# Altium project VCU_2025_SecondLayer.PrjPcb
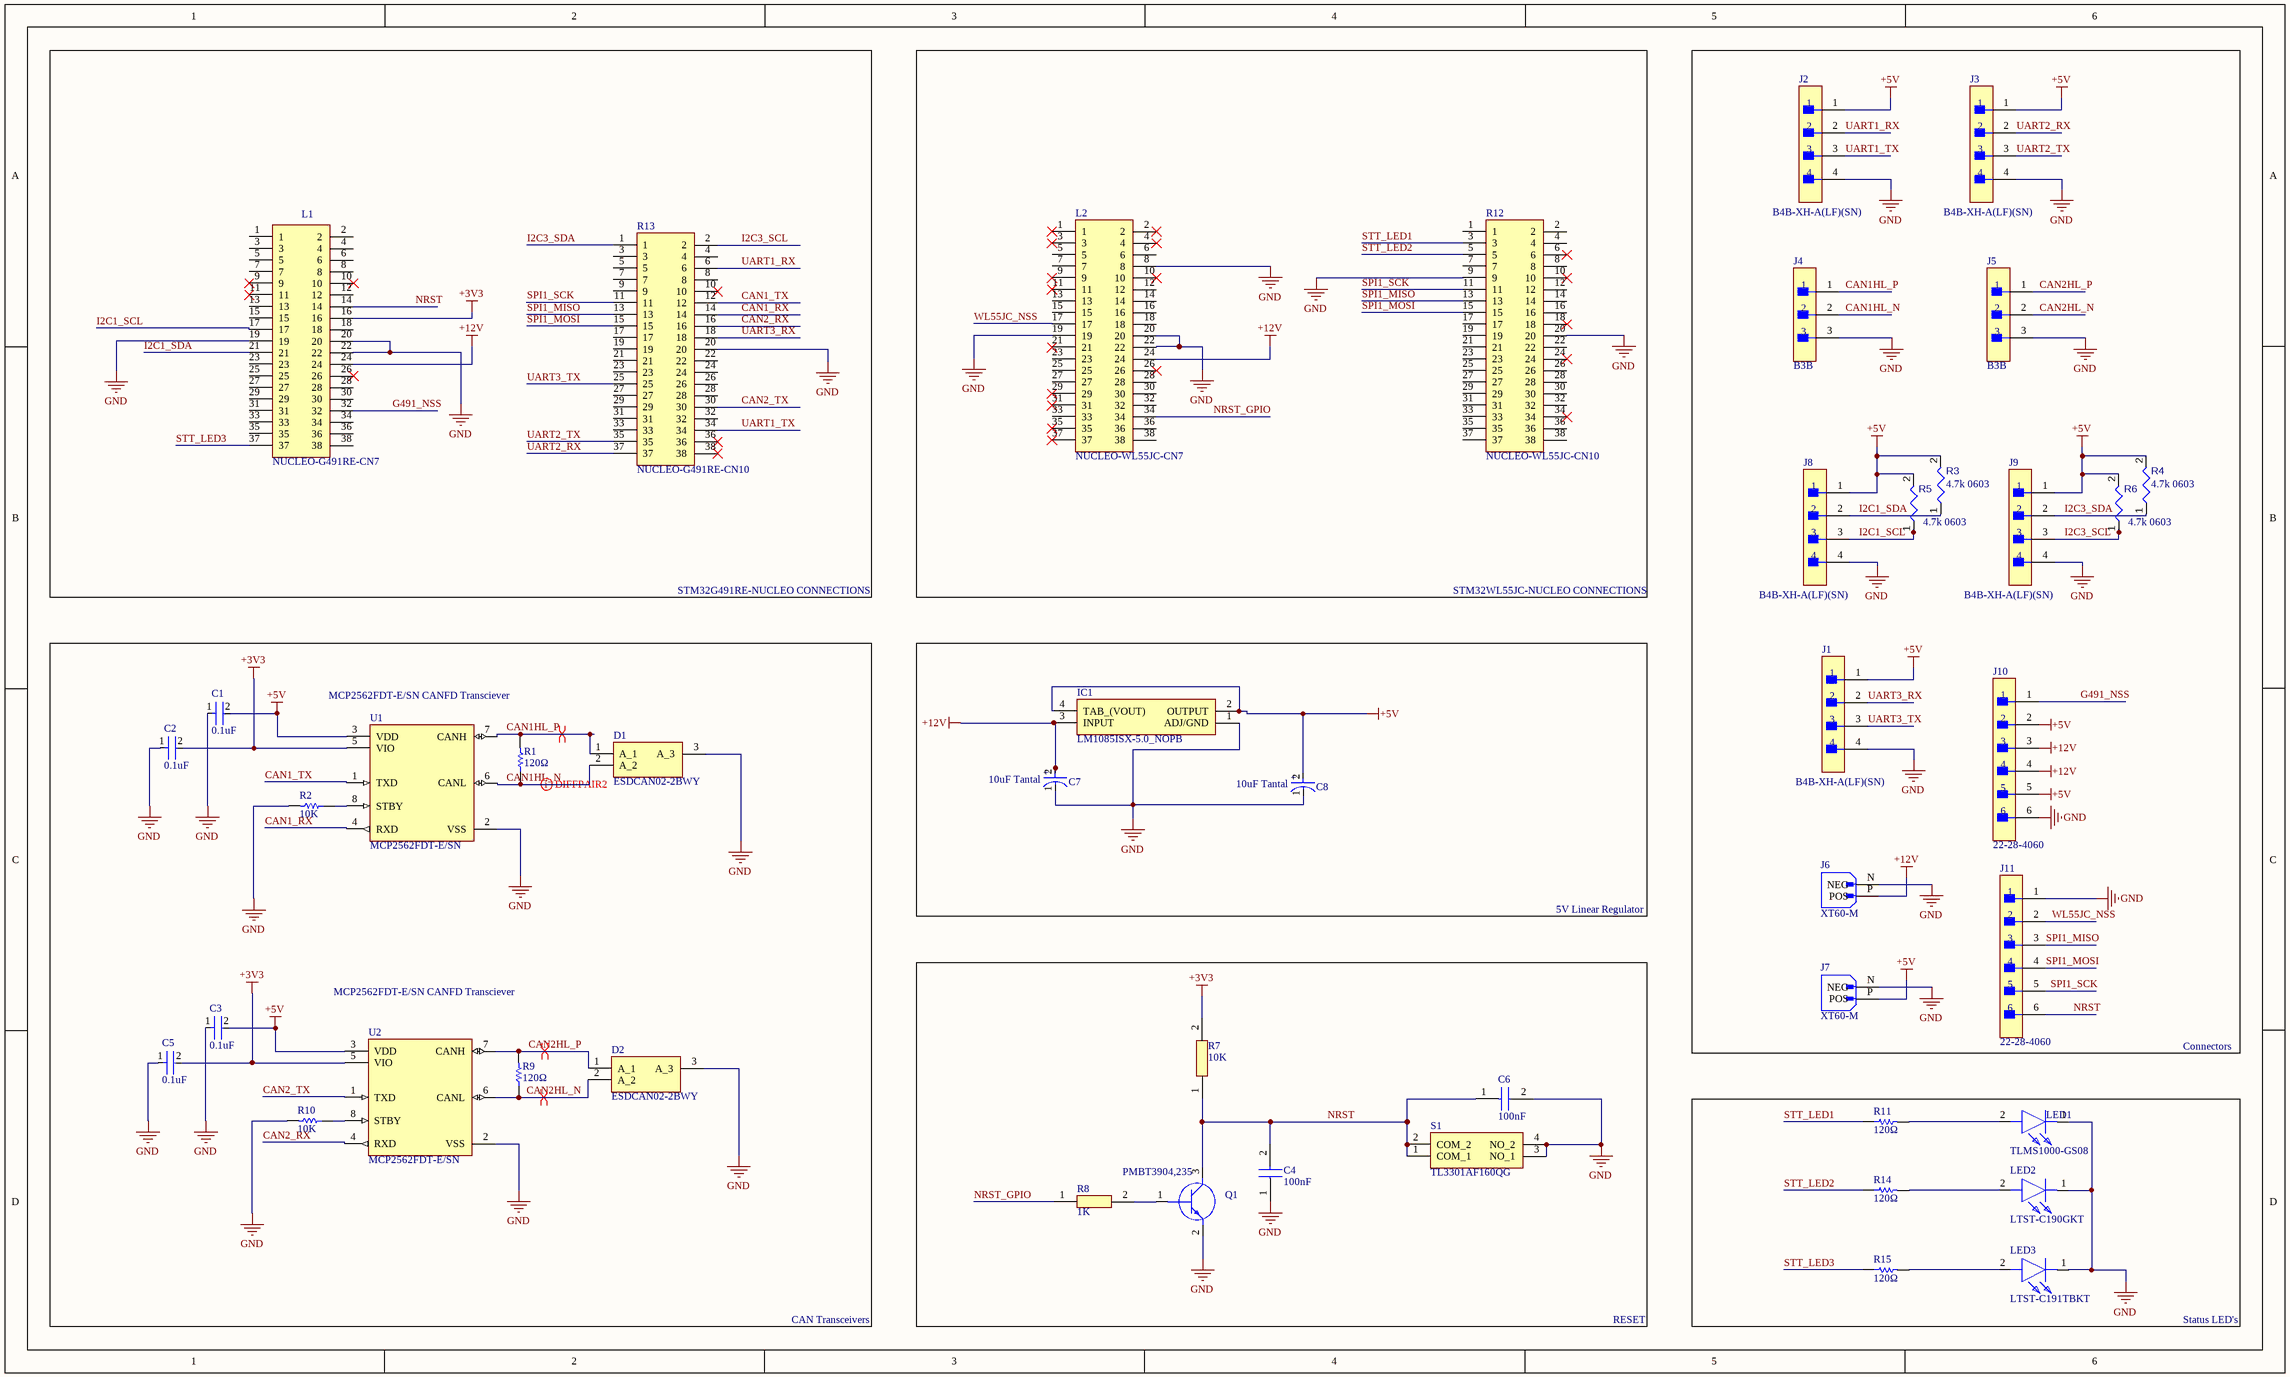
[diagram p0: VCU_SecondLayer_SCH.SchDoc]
1 sheet, 46 parts. Net scope: global (net labels, ports and power ports of the same name join across sheets).
Board file: VCU_SecondLayer_PCB.PcbDoc

## Sheet VCU_SecondLayer_SCH.SchDoc
size 500 x 299 mm; SheetNumber: 1; SheetTotal: 1

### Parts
C1  0.1uF  [FP-C0603C-CF-MFG]
C2  0.1uF  [FP-C0603C-CF-MFG]
C3  0.1uF  [FP-C0603C-CF-MFG]
C4  100nF  [CAPC1608X97N]
C5  0.1uF  [FP-C0603C-CF-MFG]
C6  100nF  [CAPC1608X97N]
C7  10uF Tantal  [FP-T491D-MFG]
C8  10uF Tantal  [FP-T491D-MFG]
D1  ESDCAN02-2BWY  [SOT65P210X110-3N]
D2  ESDCAN02-2BWY  [SOT65P210X110-3N]
IC1  LM1085ISX-5.0_NOPB  [KTT0003B]
J1  B4B-XH-A(LF)(SN)  [FP-B4B-XH-A_LF_SN-MFG]
J2  B4B-XH-A(LF)(SN)  [FP-B4B-XH-A_LF_SN-MFG]
J3  B4B-XH-A(LF)(SN)  [FP-B4B-XH-A_LF_SN-MFG]
J4  B3B  [FP-B3B-ZR_LF_SN-MFG]
J5  B3B  [FP-B3B-ZR_LF_SN-MFG]
J6  XT60-M  [XT60-M-Footprint-1]
J7  XT60-M  [XT60-M-Footprint-1]
J8  B4B-XH-A(LF)(SN)  [FP-B4B-XH-A_LF_SN-MFG]
J9  B4B-XH-A(LF)(SN)  [FP-B4B-XH-A_LF_SN-MFG]
J10  22-28-4060  [FP-22-28-4060-MFG]
J11  22-28-4060  [FP-22-28-4060-MFG]
L1  NUCLEO-G491RE-CN7  [CES-119-XX-X-D]
L2  NUCLEO-WL55JC-CN7  [CES-119-XX-X-D]
LED1  TLMS1000-GS08  [LEDC1608X65N]
LED2  LTST-C190GKT  [LEDC1608X90N]
LED3  LTST-C191TBKT  [LEDC1608X65N]
Q1  PMBT3904,235  [SOT95P230X110-3N]
R1  120Ω  [RESC1609X55X30ML15T15]
R2  10K  [RESC1609X55X30ML15T15]
R3  value 4.7k 0603  [RESC1608X55X25ML10T15]  (hidden comment: Resistor 10k +/-1% 0603 100 mW)
R4  value 4.7k 0603  [RESC1608X55X25ML10T15]  (hidden comment: Resistor 10k +/-1% 0603 100 mW)
R5  value 4.7k 0603  [RESC1608X55X25ML10T15]  (hidden comment: Resistor 10k +/-1% 0603 100 mW)
R6  value 4.7k 0603  [RESC1608X55X25ML10T15]  (hidden comment: Resistor 10k +/-1% 0603 100 mW)
R7  10K  [RESC1608X55N]
R8  1K  [RESC1608X55N]
R9  120Ω  [RESC1609X55X30ML15T15]
R10  10K  [RESC1609X55X30ML15T15]
R11  120Ω  [RESC1609X55X30ML15T15]
R12  NUCLEO-WL55JC-CN10  [CES-119-XX-X-D]
R13  NUCLEO-G491RE-CN10  [CES-119-XX-X-D]
R14  120Ω  [RESC1609X55X30ML15T15]
R15  120Ω  [RESC1609X55X30ML15T15]
S1  TL3301AF160QG  [TL3301AF160QG]
U1  MCP2562FDT-E/SN  [FP-C04-057-SN-MFG]
U2  MCP2562FDT-E/SN  [FP-C04-057-SN-MFG]

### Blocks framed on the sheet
STM32G491RE-NUCLEO CONNECTIONS: L1 R13
STM32WL55JC-NUCLEO CONNECTIONS: L2 R12
Connectors: J1-J11 R3-R6
5V Linear Regulator: C7 C8 IC1
RESET: C4 C6 Q1 R7 R8 S1
Status LED's: LED1-LED3 R11 R14 R15

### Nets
+3V3: C2.2 C5.2 L1.16 R7.2 U1.5(VIO) U2.5(VIO)
+5V: C1.2 C3.2 C8.2(A) IC1.2(OUTPUT) IC1.4(TAB_(VOUT)) J1.1 J2.1 J3.1 J7.P(POS) J8.1 J9.1 J10.2 J10.5 R3.2 R4.2 R5.2 R6.2 U1.3(VDD) U2.3(VDD)
+12V: C7.2(A) IC1.3(INPUT) J6.P(POS) J10.3 J10.4 L1.24 L2.24
GND: C1.1 C2.1 C3.1 C4.1 C5.1 C6.2 C7.1(C) C8.1(C) D1.3(A_3) D2.3(A_3) IC1.1(ADJ/GND) J1.4 J2.4 J3.4 J4.3 J5.3 J6.N(NEG) J7.N(NEG) J8.4 J9.4 J10.6 J11.1 L1.19 L1.20 L1.22 L2.8 L2.19 L2.20 L2.22 LED1.1(K) LED2.1(K) LED3.1(K) Q1.2(E) R2.2 R10.2 R12.9 R12.20 R13.20 S1.3(NO_1) S1.4(NO_2) U1.2(VSS) U2.2(VSS)
CAN1_RX: R13.14 U1.4(RXD)
CAN1_TX: R13.12 U1.1(TXD)
CAN1HL_N: D1.2(A_2) J4.2 R1.1 U1.6(CANL)
CAN1HL_P: D1.1(A_1) J4.1 R1.2 U1.7(CANH)
CAN2_RX: R13.16 U2.4(RXD)
CAN2_TX: R13.30 U2.1(TXD)
CAN2HL_N: D2.2(A_2) J5.2 R9.1 U2.6(CANL)
CAN2HL_P: D2.1(A_1) J5.1 R9.2 U2.7(CANH)
G491_NSS: J10.1 L1.32
I2C1_SCL: J8.3 L1.17 R5.1
I2C1_SDA: J8.2 L1.21 R3.1
I2C3_SCL: J9.3 R6.1 R13.2
I2C3_SDA: J9.2 R4.1 R13.1
NRST: C4.2 C6.1 J11.6 L1.14 Q1.3(C) R7.1 S1.1(COM_1) S1.2(COM_2)
NRST_GPIO: L2.34 R8.1
SPI1_MISO: J11.3 R12.13 R13.13
SPI1_MOSI: J11.4 R12.15 R13.15
SPI1_SCK: J11.5 R12.11 R13.11
STT_LED1: R11.1 R12.3
STT_LED2: R12.5 R14.1
STT_LED3: L1.37 R15.1
UART1_RX: J2.2 R13.6
UART1_TX: J2.3 R13.34
UART2_RX: J3.2 R13.37
UART2_TX: J3.3 R13.35
UART3_RX: J1.2 R13.18
UART3_TX: J1.3 R13.25
WL55JC_NSS: J11.2 L2.17
NetLED1_2: LED1.2(A) R11.2
NetLED2_2: LED2.2(A) R14.2
NetLED3_2: LED3.2(A) R15.2
NetQ1_1: Q1.1(B) R8.2
NetR2_1: R2.1 U1.8(STBY)
NetR10_1: R10.1 U2.8(STBY)

Not connected (* = marked no-connect by the designer): L1 1 2 3 4 5 6 7 8 9* 10* 11* 12 13 15 18 23 25 26* 27 28 29 30 31 33 34 35 36 38; L2 1* 2* 3* 4* 5 6 7 9* 10* 11* 12 13 14 15 16 18 21* 23 25 26* 27 28 29* 30 31* 32 33 35* 36 37* 38; R12 1 2 4 6* 7 8 10* 12 14 16 17 18* 19 21 22 23 24* 25 26 27 28 29 30 31 32 33 34* 35 36 37 38; R13 3 4 5 7 8 9 10* 17 19 21 22 23 24 26 27 28 29 31 32 33 36* 38*

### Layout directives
differential pair: CAN1HL_N, CAN1HL_P, CAN2HL_N, CAN2HL_P

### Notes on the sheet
- MCP2562FDT-E/SN CANFD Transciever
- CAN Transceivers

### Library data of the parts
C1-C3 C5 = CMP-2006-03068-2: CAP CER 0.1UF 50V 20% X7R 0603; Manufacturer Part Number: C0603C104M5RACTU; Manufacturer: KEMET; Material: Ceramic; Tolerance: 0.2; Value: 0.10 μF; Temperature Coefficient: 30ppm/°C; Automotive Grade: Grade 1
C4 C6 = VJ0603Y104JXJAC: Manufacturer_Name: Vishay
C7 C8 = CMP-001-00086-1: Cap Tant Solid 10uF 25V D CASE 10% (7.3 X 4.3 X 2.8mm) Inward L SMD 7343-31 1 Ohm 125C T/R / T491D106K025AT
D1 D2 = ESDCAN02-2BWY: TVS Diode (Bi-directional); Manufacturer_Name: STMicroelectronics
IC1 = LM1085ISX-5.0_NOPB: Integrated Circuit; Manufacturer_Name: Texas Instruments; Manufacturer_Part_Number: LM1085ISX-5.0/NOPB
J1-J3 J8 J9 = CMP-002-00072-1: Header for PCB; pitch 2.50mm; 4-contacts; THT male; top entry; 250V/3A
J4 J5 = CMP-002-00073-3: CONN HEADER ZH TOP 3POS
J6 J7 = CMP-002-00074-2: XT60 Male Connector
J10 J11 = CMP-04776-000763-1: CONN HEADER VERT 6POS 2.54MM; Voltage Rating: 250V; Current Rating: 4A; Number of Contacts: 6; Max Voltage Rating (DC): 250.25kV; Gender: Male; Contact Resistance: 20mR; Connector Type: Male Pin
L1 L2 R12 R13 = CES-119-02-T-D: Connector; Manufacturer_Name: SAMTEC
LED1 = TLMS1000-GS08: LED; Manufacturer_Name: Vishay
LED2 = LTST-C190GKT: LED; Manufacturer_Name: Lite-On
LED3 = LTST-C191TBKT: LED; Manufacturer_Name: Lite-On
Q1 = PMBT3904,235: Transistor BJT NPN; Manufacturer_Name: Nexperia
R1 R9 R11 R14 R15 = CMP-2000-00213-2: Chip Resistor, 120 Ohm, +/- 1%, 0.1 W, -55 to 155 degC, 0603 (1608 Metric), RoHS, Tape and Reel; Manufacturer: Panasonic; Power Rating: 100mW; Voltage Rating (DC): 75V; Resistance: 120Ohm; Temperature Coefficient: 100ppm/degreesC
R2 R10 = CMP-2000-00213-2: RC0603FR0710KL 0603 10K Resistor; Manufacturer: Panasonic; Tolerance: 1%; Power Rating: 100mW; Voltage Rating (DC): 75V; Resistance: 120Ohm; Temperature Coefficient: 100ppm/degreesC
R3-R6 = CMP-009-00017-5: Chip Resistor, 10 KOhm, +/- 1%, 01 W, -55 to 155 degC, 0603 (1608 Metric) / RC0603FR-0710KL; Voltage Rating: 50V; Power: 100mW
R7 = RC0603FR0710KL: Manufacturer_Name: KEMET
R8 = RC0603FR-071KL: Manufacturer_Name: YAGEO
S1 = TL3301AF160QG: Switch; Manufacturer_Name: E-Switch
U1 U2 = CMP-06279-000005-1: IC TRANSCEIVER 1/1 8SOIC; Operating Supply Current: 70mA; Data Rate: 8Mbps; Number of Transceivers: 1; Receiver Hysteresis: 200mV; Max Supply Voltage: 5.5V; Min Supply Voltage: 4.5V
